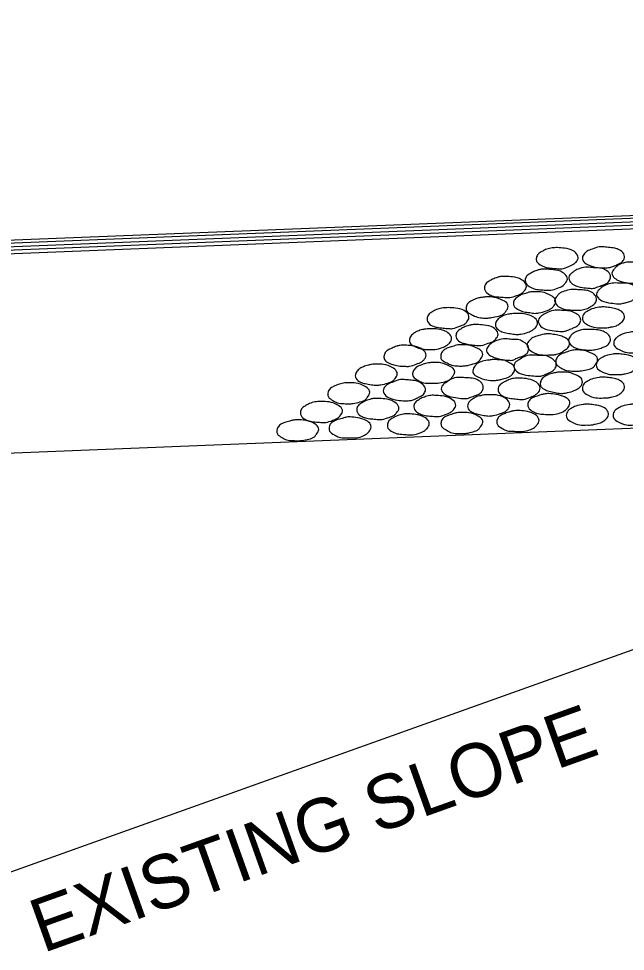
# Model space of a CAD drawing. Extents: x 3287 to 1767681, y -265 to 581440.
# Drawn here: x 3336.53 to 3350.12, y 48.55 to 69.44 of the extents above; entities that cross this region are included whole.
import ezdxf

# ---------------------------------------------------------------- set-up
doc = ezdxf.new("R2010")
doc.units = 0
doc.layers.add('R_Border PE', color=7, linetype='Continuous')

msp = doc.modelspace()

# ---------------------------------------------------------------- linework, layer by layer
at = {"layer": 'R_Border PE'}
for p, q in [((3332.136, 64.247), (3460.643, 69.373)), ((3332.286, 64.318), (3460.506, 69.441)), ((3331.799, 64.078), (3460.936, 69.227)), ((3331.966, 64.158), (3460.793, 69.3)), ((3331.631, 63.991), (3461.081, 69.155)), ((3321.917, 59.136), (3372.148, 61.138)), ((3361.044, 59.148), (3331.515, 48.595))]:
    msp.add_line(p, q, dxfattribs=at)
for points in [[(3348.599, 64.313), (3348.762, 64.298), (3348.958, 64.243), (3349.05, 64.146), (3349.066, 64.093), (3349.021, 63.989), (3348.973, 63.949), (3348.861, 63.891), (3348.699, 63.839), (3348.613, 63.839), (3348.487, 63.85), (3348.353, 63.868), (3348.245, 63.912), (3348.141, 63.994), (3348.128, 64.062), (3348.157, 64.148), (3348.233, 64.214), (3348.311, 64.255), (3348.421, 64.294), (3348.487, 64.306), (3348.599, 64.313)], [(3349.636, 63.857), (3349.469, 63.87), (3349.278, 63.934), (3349.172, 64.023), (3349.16, 64.086), (3349.21, 64.183), (3349.267, 64.232), (3349.382, 64.279), (3349.537, 64.331), (3349.615, 64.331), (3349.744, 64.318), (3349.885, 64.298), (3349.987, 64.261), (3350.087, 64.174), (3350.105, 64.114), (3350.076, 64.02), (3350, 63.962), (3349.924, 63.921), (3349.812, 63.878), (3349.744, 63.863), (3349.636, 63.857)], [(3350.299, 63.514), (3350.132, 63.528), (3349.935, 63.593), (3349.841, 63.677), (3349.823, 63.737), (3349.878, 63.836), (3349.93, 63.891), (3350.037, 63.954), (3350.199, 63.985), (3350.275, 63.985), (3350.399, 63.989), (3350.542, 63.967), (3350.653, 63.918), (3350.752, 63.831), (3350.768, 63.776), (3350.736, 63.672), (3350.661, 63.616), (3350.584, 63.583), (3350.474, 63.545), (3350.399, 63.522), (3350.299, 63.514)], [(3348.345, 63.829), (3348.51, 63.818), (3348.717, 63.758), (3348.811, 63.664), (3348.827, 63.608), (3348.77, 63.506), (3348.728, 63.462), (3348.607, 63.405), (3348.457, 63.358), (3348.368, 63.358), (3348.241, 63.365), (3348.104, 63.384), (3348, 63.426), (3347.895, 63.514), (3347.881, 63.577), (3347.911, 63.669), (3347.987, 63.727), (3348.063, 63.769), (3348.172, 63.811), (3348.241, 63.826), (3348.345, 63.829)], [(3349.325, 63.401), (3349.162, 63.42), (3348.968, 63.475), (3348.874, 63.567), (3348.856, 63.625), (3348.9, 63.724), (3348.961, 63.773), (3349.066, 63.831), (3349.23, 63.873), (3349.307, 63.873), (3349.437, 63.86), (3349.578, 63.85), (3349.684, 63.808), (3349.778, 63.718), (3349.794, 63.659), (3349.764, 63.566), (3349.694, 63.506), (3349.612, 63.472), (3349.502, 63.43), (3349.437, 63.405), (3349.325, 63.401)], [(3347.433, 63.664), (3347.598, 63.656), (3347.8, 63.593), (3347.894, 63.498), (3347.908, 63.443), (3347.86, 63.341), (3347.806, 63.292), (3347.69, 63.236), (3347.533, 63.195), (3347.452, 63.195), (3347.326, 63.205), (3347.185, 63.219), (3347.083, 63.258), (3346.981, 63.349), (3346.968, 63.41), (3346.999, 63.502), (3347.072, 63.562), (3347.148, 63.603), (3347.253, 63.646), (3347.326, 63.663), (3347.433, 63.664)], [(3349.969, 63.05), (3349.798, 63.071), (3349.597, 63.122), (3349.492, 63.216), (3349.477, 63.271), (3349.537, 63.37), (3349.589, 63.417), (3349.713, 63.486), (3349.866, 63.519), (3349.945, 63.519), (3350.071, 63.515), (3350.21, 63.502), (3350.317, 63.456), (3350.406, 63.363), (3350.422, 63.305), (3350.391, 63.216), (3350.32, 63.153), (3350.247, 63.114), (3350.142, 63.082), (3350.076, 63.064), (3349.969, 63.05)], [(3348.089, 63.318), (3348.258, 63.315), (3348.455, 63.239), (3348.546, 63.16), (3348.563, 63.095), (3348.51, 62.99), (3348.46, 62.946), (3348.351, 62.894), (3348.186, 62.849), (3348.107, 62.839), (3347.981, 62.855), (3347.847, 62.876), (3347.737, 62.92), (3347.632, 62.998), (3347.617, 63.064), (3347.648, 63.153), (3347.729, 63.218), (3347.801, 63.261), (3347.911, 63.295), (3347.981, 63.315), (3348.089, 63.318)], [(3349.018, 62.91), (3348.846, 62.92), (3348.647, 62.975), (3348.552, 63.075), (3348.536, 63.129), (3348.596, 63.226), (3348.638, 63.278), (3348.751, 63.333), (3348.906, 63.375), (3349, 63.375), (3349.123, 63.365), (3349.259, 63.355), (3349.364, 63.315), (3349.461, 63.221), (3349.477, 63.163), (3349.45, 63.071), (3349.377, 63.011), (3349.301, 62.964), (3349.183, 62.925), (3349.123, 62.914), (3349.018, 62.91)], [(3347.02, 63.21), (3347.185, 63.198), (3347.381, 63.129), (3347.486, 63.046), (3347.497, 62.993), (3347.445, 62.881), (3347.395, 62.825), (3347.28, 62.778), (3347.127, 62.744), (3347.041, 62.734), (3346.916, 62.737), (3346.771, 62.766), (3346.674, 62.813), (3346.57, 62.891), (3346.556, 62.952), (3346.583, 63.046), (3346.659, 63.111), (3346.734, 63.148), (3346.845, 63.185), (3346.915, 63.198), (3347.02, 63.21)], [(3346.151, 62.967), (3346.32, 62.956), (3346.512, 62.901), (3346.609, 62.805), (3346.62, 62.747), (3346.574, 62.647), (3346.525, 62.6), (3346.412, 62.551), (3346.252, 62.498), (3346.169, 62.498), (3346.045, 62.509), (3345.907, 62.527), (3345.799, 62.561), (3345.695, 62.655), (3345.682, 62.715), (3345.713, 62.808), (3345.787, 62.867), (3345.865, 62.914), (3345.977, 62.949), (3346.045, 62.961), (3346.151, 62.967)], [(3348.659, 62.435), (3348.486, 62.453), (3348.292, 62.506), (3348.19, 62.603), (3348.173, 62.66), (3348.227, 62.766), (3348.282, 62.808), (3348.393, 62.867), (3348.555, 62.91), (3348.634, 62.91), (3348.759, 62.901), (3348.897, 62.891), (3349.011, 62.838), (3349.105, 62.757), (3349.123, 62.69), (3349.089, 62.597), (3349.018, 62.54), (3348.937, 62.503), (3348.833, 62.462), (3348.759, 62.438), (3348.659, 62.435)], [(3349.629, 62.516), (3349.461, 62.519), (3349.278, 62.584), (3349.172, 62.674), (3349.16, 62.726), (3349.204, 62.838), (3349.267, 62.884), (3349.374, 62.938), (3349.537, 62.975), (3349.615, 62.983), (3349.743, 62.972), (3349.88, 62.951), (3349.987, 62.914), (3350.087, 62.828), (3350.105, 62.771), (3350.076, 62.677), (3350, 62.609), (3349.924, 62.563), (3349.809, 62.535), (3349.736, 62.519), (3349.629, 62.516)], [(3347.68, 62.838), (3347.852, 62.831), (3348.042, 62.771), (3348.141, 62.682), (3348.157, 62.624), (3348.109, 62.516), (3348.054, 62.472), (3347.947, 62.417), (3347.78, 62.375), (3347.699, 62.367), (3347.58, 62.381), (3347.444, 62.402), (3347.332, 62.44), (3347.227, 62.525), (3347.214, 62.584), (3347.242, 62.677), (3347.319, 62.744), (3347.392, 62.789), (3347.504, 62.818), (3347.583, 62.831), (3347.68, 62.838)], [(3345.757, 62.495), (3345.925, 62.488), (3346.121, 62.422), (3346.214, 62.334), (3346.231, 62.281), (3346.182, 62.171), (3346.129, 62.126), (3346.02, 62.071), (3345.859, 62.03), (3345.773, 62.026), (3345.651, 62.032), (3345.517, 62.053), (3345.406, 62.095), (3345.3, 62.174), (3345.286, 62.241), (3345.315, 62.328), (3345.397, 62.401), (3345.467, 62.44), (3345.58, 62.475), (3345.655, 62.488), (3345.757, 62.495)], [(3346.79, 62.588), (3346.962, 62.577), (3347.161, 62.522), (3347.256, 62.423), (3347.274, 62.368), (3347.221, 62.267), (3347.172, 62.22), (3347.054, 62.169), (3346.897, 62.119), (3346.818, 62.119), (3346.69, 62.131), (3346.551, 62.157), (3346.449, 62.184), (3346.342, 62.275), (3346.328, 62.338), (3346.358, 62.427), (3346.438, 62.488), (3346.512, 62.533), (3346.619, 62.567), (3346.69, 62.585), (3346.79, 62.588)], [(3349.317, 62.013), (3349.159, 62.029), (3348.964, 62.085), (3348.871, 62.173), (3348.853, 62.233), (3348.892, 62.328), (3348.952, 62.386), (3349.055, 62.443), (3349.223, 62.48), (3349.304, 62.48), (3349.435, 62.475), (3349.573, 62.459), (3349.678, 62.411), (3349.775, 62.323), (3349.791, 62.26), (3349.762, 62.171), (3349.691, 62.108), (3349.608, 62.072), (3349.495, 62.038), (3349.432, 62.024), (3349.317, 62.013)], [(3347.5, 61.791), (3347.337, 61.809), (3347.137, 61.87), (3347.028, 61.959), (3347.014, 62.022), (3347.067, 62.119), (3347.124, 62.169), (3347.238, 62.229), (3347.392, 62.267), (3347.479, 62.267), (3347.602, 62.255), (3347.746, 62.247), (3347.848, 62.194), (3347.944, 62.111), (3347.958, 62.045), (3347.928, 61.953), (3347.856, 61.898), (3347.784, 61.867), (3347.67, 61.825), (3347.606, 61.793), (3347.5, 61.791)], [(3348.4, 61.907), (3348.235, 61.911), (3348.034, 61.98), (3347.937, 62.072), (3347.921, 62.131), (3347.978, 62.234), (3348.029, 62.281), (3348.141, 62.328), (3348.304, 62.372), (3348.385, 62.381), (3348.51, 62.368), (3348.644, 62.344), (3348.751, 62.305), (3348.856, 62.226), (3348.874, 62.165), (3348.838, 62.069), (3348.759, 62.014), (3348.688, 61.959), (3348.583, 61.924), (3348.508, 61.911), (3348.4, 61.907)], [(3350.333, 61.959), (3350.165, 61.962), (3349.982, 62.027), (3349.875, 62.118), (3349.864, 62.17), (3349.908, 62.281), (3349.971, 62.328), (3350.077, 62.381), (3350.241, 62.419), (3350.319, 62.427), (3350.446, 62.415), (3350.584, 62.394), (3350.691, 62.357), (3350.791, 62.271), (3350.809, 62.215), (3350.78, 62.121), (3350.704, 62.053), (3350.627, 62.006), (3350.513, 61.979), (3350.44, 61.962), (3350.333, 61.959)], [(3345.179, 62.126), (3345.344, 62.114), (3345.548, 62.05), (3345.647, 61.956), (3345.661, 61.903), (3345.606, 61.794), (3345.561, 61.755), (3345.438, 61.704), (3345.284, 61.653), (3345.202, 61.653), (3345.074, 61.66), (3344.938, 61.684), (3344.833, 61.723), (3344.731, 61.804), (3344.716, 61.875), (3344.746, 61.962), (3344.822, 62.027), (3344.898, 62.063), (3345.004, 62.105), (3345.074, 62.123), (3345.179, 62.126)], [(3346.452, 62.137), (3346.617, 62.126), (3346.818, 62.053), (3346.915, 61.974), (3346.928, 61.919), (3346.873, 61.807), (3346.832, 61.759), (3346.711, 61.705), (3346.559, 61.668), (3346.468, 61.66), (3346.345, 61.663), (3346.201, 61.691), (3346.103, 61.742), (3345.999, 61.815), (3345.988, 61.885), (3346.017, 61.974), (3346.088, 62.038), (3346.168, 62.072), (3346.278, 62.108), (3346.342, 62.126), (3346.452, 62.137)], [(3348.11, 61.432), (3347.944, 61.45), (3347.745, 61.503), (3347.644, 61.6), (3347.627, 61.653), (3347.678, 61.759), (3347.742, 61.797), (3347.848, 61.867), (3348.012, 61.903), (3348.096, 61.903), (3348.217, 61.894), (3348.353, 61.888), (3348.463, 61.836), (3348.558, 61.754), (3348.575, 61.684), (3348.541, 61.594), (3348.465, 61.532), (3348.393, 61.5), (3348.285, 61.45), (3348.214, 61.433), (3348.11, 61.432)], [(3349.028, 62.021), (3349.188, 62.009), (3349.396, 61.932), (3349.489, 61.856), (3349.503, 61.794), (3349.45, 61.691), (3349.411, 61.636), (3349.291, 61.584), (3349.138, 61.552), (3349.044, 61.543), (3348.921, 61.547), (3348.777, 61.568), (3348.68, 61.621), (3348.579, 61.699), (3348.563, 61.763), (3348.599, 61.856), (3348.665, 61.919), (3348.743, 61.951), (3348.858, 61.99), (3348.918, 62.009), (3349.028, 62.021)], [(3349.94, 61.468), (3349.772, 61.472), (3349.589, 61.536), (3349.482, 61.627), (3349.471, 61.679), (3349.515, 61.79), (3349.578, 61.837), (3349.685, 61.89), (3349.848, 61.928), (3349.926, 61.936), (3350.054, 61.924), (3350.191, 61.903), (3350.298, 61.866), (3350.398, 61.78), (3350.416, 61.724), (3350.387, 61.63), (3350.311, 61.562), (3350.235, 61.515), (3350.12, 61.488), (3350.047, 61.472), (3349.94, 61.468)], [(3344.543, 61.702), (3344.708, 61.697), (3344.902, 61.628), (3345, 61.54), (3345.014, 61.485), (3344.967, 61.377), (3344.914, 61.328), (3344.805, 61.277), (3344.644, 61.238), (3344.556, 61.23), (3344.433, 61.239), (3344.297, 61.265), (3344.189, 61.298), (3344.09, 61.383), (3344.074, 61.443), (3344.105, 61.534), (3344.178, 61.605), (3344.254, 61.645), (3344.369, 61.678), (3344.437, 61.697), (3344.543, 61.702)], [(3345.82, 61.742), (3345.991, 61.731), (3346.187, 61.658), (3346.287, 61.577), (3346.303, 61.527), (3346.245, 61.416), (3346.2, 61.364), (3346.077, 61.307), (3345.925, 61.277), (3345.846, 61.273), (3345.719, 61.273), (3345.575, 61.293), (3345.472, 61.344), (3345.372, 61.422), (3345.357, 61.49), (3345.391, 61.577), (3345.461, 61.645), (3345.54, 61.678), (3345.648, 61.717), (3345.716, 61.731), (3345.82, 61.742)], [(3347.185, 61.335), (3347.017, 61.348), (3346.818, 61.416), (3346.716, 61.497), (3346.708, 61.552), (3346.753, 61.658), (3346.806, 61.713), (3346.92, 61.765), (3347.077, 61.794), (3347.161, 61.804), (3347.285, 61.797), (3347.429, 61.78), (3347.526, 61.734), (3347.628, 61.652), (3347.646, 61.59), (3347.614, 61.497), (3347.538, 61.429), (3347.467, 61.398), (3347.357, 61.364), (3347.29, 61.348), (3347.185, 61.335)], [(3348.688, 61.522), (3348.858, 61.516), (3349.041, 61.446), (3349.151, 61.364), (3349.16, 61.301), (3349.115, 61.196), (3349.052, 61.149), (3348.948, 61.099), (3348.782, 61.055), (3348.706, 61.045), (3348.583, 61.06), (3348.448, 61.086), (3348.332, 61.124), (3348.233, 61.204), (3348.217, 61.27), (3348.248, 61.357), (3348.321, 61.425), (3348.397, 61.467), (3348.51, 61.5), (3348.586, 61.516), (3348.688, 61.522)], [(3343.921, 61.281), (3344.087, 61.277), (3344.283, 61.207), (3344.382, 61.124), (3344.399, 61.073), (3344.344, 60.959), (3344.296, 60.904), (3344.178, 60.854), (3344.024, 60.819), (3343.943, 60.814), (3343.815, 60.817), (3343.67, 60.838), (3343.571, 60.888), (3343.472, 60.966), (3343.455, 61.029), (3343.487, 61.124), (3343.56, 61.189), (3343.637, 61.226), (3343.747, 61.262), (3343.812, 61.277), (3343.921, 61.281)], [(3345.184, 60.882), (3345.017, 60.893), (3344.818, 60.955), (3344.713, 61.048), (3344.699, 61.107), (3344.75, 61.21), (3344.807, 61.255), (3344.928, 61.304), (3345.089, 61.356), (3345.168, 61.356), (3345.294, 61.344), (3345.431, 61.328), (3345.533, 61.285), (3345.626, 61.2), (3345.645, 61.136), (3345.613, 61.042), (3345.545, 60.985), (3345.475, 60.95), (3345.367, 60.9), (3345.287, 60.885), (3345.184, 60.882)], [(3346.483, 60.93), (3346.316, 60.951), (3346.121, 61.003), (3346.015, 61.097), (3345.998, 61.15), (3346.053, 61.255), (3346.108, 61.294), (3346.223, 61.365), (3346.379, 61.404), (3346.465, 61.404), (3346.586, 61.393), (3346.729, 61.383), (3346.837, 61.335), (3346.925, 61.247), (3346.941, 61.183), (3346.912, 61.094), (3346.842, 61.029), (3346.768, 60.998), (3346.654, 60.959), (3346.591, 60.935), (3346.483, 60.93)], [(3347.737, 61.387), (3347.898, 61.377), (3348.104, 61.314), (3348.199, 61.222), (3348.214, 61.16), (3348.164, 61.06), (3348.11, 61.016), (3347.997, 60.963), (3347.84, 60.913), (3347.754, 60.913), (3347.627, 60.925), (3347.491, 60.948), (3347.384, 60.982), (3347.289, 61.069), (3347.271, 61.134), (3347.302, 61.226), (3347.373, 61.281), (3347.452, 61.322), (3347.562, 61.369), (3347.627, 61.383), (3347.737, 61.387)], [(3349.629, 60.945), (3349.461, 60.948), (3349.278, 61.013), (3349.172, 61.103), (3349.16, 61.155), (3349.204, 61.267), (3349.267, 61.313), (3349.374, 61.367), (3349.537, 61.404), (3349.615, 61.412), (3349.743, 61.401), (3349.88, 61.38), (3349.987, 61.343), (3350.087, 61.257), (3350.105, 61.2), (3350.076, 61.106), (3350, 61.038), (3349.924, 60.992), (3349.809, 60.964), (3349.736, 60.948), (3349.629, 60.945)], [(3347.062, 61.016), (3347.227, 61.011), (3347.423, 60.945), (3347.517, 60.856), (3347.533, 60.799), (3347.488, 60.689), (3347.436, 60.644), (3347.326, 60.594), (3347.161, 60.55), (3347.077, 60.54), (3346.955, 60.553), (3346.821, 60.578), (3346.711, 60.618), (3346.606, 60.699), (3346.591, 60.764), (3346.62, 60.851), (3346.701, 60.919), (3346.771, 60.963), (3346.883, 60.995), (3346.959, 61.011), (3347.062, 61.016)], [(3348.41, 61.042), (3348.578, 61.024), (3348.762, 60.966), (3348.871, 60.88), (3348.88, 60.822), (3348.835, 60.722), (3348.774, 60.667), (3348.665, 60.61), (3348.508, 60.574), (3348.424, 60.574), (3348.3, 60.578), (3348.164, 60.594), (3348.054, 60.641), (3347.952, 60.73), (3347.936, 60.793), (3347.966, 60.882), (3348.039, 60.948), (3348.117, 60.977), (3348.23, 61.013), (3348.304, 61.032), (3348.41, 61.042)], [(3343.312, 60.867), (3343.485, 60.854), (3343.67, 60.793), (3343.773, 60.702), (3343.786, 60.641), (3343.731, 60.54), (3343.683, 60.497), (3343.571, 60.443), (3343.411, 60.395), (3343.333, 60.395), (3343.204, 60.405), (3343.068, 60.421), (3342.96, 60.463), (3342.858, 60.55), (3342.845, 60.617), (3342.872, 60.704), (3342.948, 60.764), (3343.024, 60.807), (3343.138, 60.848), (3343.204, 60.861), (3343.312, 60.867)], [(3344.571, 60.932), (3344.736, 60.922), (3344.938, 60.861), (3345.035, 60.767), (3345.051, 60.709), (3344.996, 60.61), (3344.949, 60.561), (3344.833, 60.51), (3344.674, 60.463), (3344.594, 60.463), (3344.466, 60.473), (3344.33, 60.492), (3344.225, 60.529), (3344.12, 60.617), (3344.108, 60.68), (3344.137, 60.77), (3344.215, 60.83), (3344.288, 60.874), (3344.399, 60.913), (3344.466, 60.93), (3344.571, 60.932)], [(3345.852, 61.003), (3346.02, 60.99), (3346.208, 60.93), (3346.313, 60.835), (3346.323, 60.775), (3346.271, 60.678), (3346.223, 60.633), (3346.111, 60.579), (3345.951, 60.529), (3345.87, 60.529), (3345.74, 60.54), (3345.606, 60.555), (3345.499, 60.599), (3345.401, 60.684), (3345.385, 60.749), (3345.414, 60.838), (3345.486, 60.898), (3345.566, 60.945), (3345.677, 60.982), (3345.74, 60.998), (3345.852, 61.003)], [(3349.269, 60.339), (3349.101, 60.342), (3348.918, 60.407), (3348.812, 60.498), (3348.8, 60.549), (3348.844, 60.661), (3348.907, 60.708), (3349.014, 60.761), (3349.177, 60.798), (3349.255, 60.807), (3349.383, 60.795), (3349.52, 60.774), (3349.627, 60.737), (3349.727, 60.651), (3349.745, 60.595), (3349.716, 60.501), (3349.64, 60.433), (3349.564, 60.386), (3349.449, 60.358), (3349.376, 60.342), (3349.269, 60.339)], [(3350.317, 60.339), (3350.148, 60.342), (3349.966, 60.407), (3349.859, 60.498), (3349.848, 60.549), (3349.891, 60.661), (3349.954, 60.708), (3350.061, 60.761), (3350.224, 60.798), (3350.302, 60.807), (3350.43, 60.795), (3350.567, 60.774), (3350.674, 60.737), (3350.775, 60.651), (3350.792, 60.595), (3350.763, 60.501), (3350.687, 60.433), (3350.611, 60.386), (3350.496, 60.358), (3350.423, 60.342), (3350.317, 60.339)], [(3346.457, 60.621), (3346.62, 60.613), (3346.824, 60.54), (3346.918, 60.461), (3346.933, 60.405), (3346.876, 60.295), (3346.837, 60.243), (3346.714, 60.189), (3346.564, 60.152), (3346.473, 60.147), (3346.35, 60.149), (3346.206, 60.173), (3346.108, 60.227), (3346.006, 60.304), (3345.993, 60.369), (3346.02, 60.461), (3346.095, 60.526), (3346.172, 60.558), (3346.284, 60.595), (3346.349, 60.613), (3346.457, 60.621)], [(3347.724, 60.663), (3347.884, 60.647), (3348.075, 60.587), (3348.173, 60.5), (3348.19, 60.443), (3348.143, 60.34), (3348.089, 60.286), (3347.979, 60.23), (3347.818, 60.194), (3347.737, 60.194), (3347.609, 60.198), (3347.473, 60.21), (3347.363, 60.262), (3347.259, 60.346), (3347.245, 60.413), (3347.277, 60.505), (3347.352, 60.565), (3347.429, 60.599), (3347.538, 60.633), (3347.614, 60.655), (3347.724, 60.663)], [(3342.777, 60.456), (3342.947, 60.443), (3343.147, 60.377), (3343.241, 60.293), (3343.256, 60.241), (3343.204, 60.13), (3343.159, 60.076), (3343.036, 60.021), (3342.884, 59.992), (3342.803, 59.986), (3342.68, 59.989), (3342.536, 60.005), (3342.431, 60.06), (3342.329, 60.138), (3342.314, 60.201), (3342.343, 60.293), (3342.418, 60.361), (3342.492, 60.395), (3342.605, 60.427), (3342.677, 60.443), (3342.777, 60.456)], [(3343.958, 60.519), (3344.123, 60.502), (3344.317, 60.44), (3344.414, 60.353), (3344.428, 60.298), (3344.385, 60.194), (3344.331, 60.144), (3344.221, 60.083), (3344.058, 60.049), (3343.974, 60.049), (3343.849, 60.052), (3343.713, 60.066), (3343.605, 60.12), (3343.498, 60.201), (3343.487, 60.267), (3343.513, 60.359), (3343.594, 60.419), (3343.663, 60.453), (3343.783, 60.485), (3343.854, 60.51), (3343.958, 60.519)], [(3345.262, 60.587), (3345.428, 60.574), (3345.616, 60.515), (3345.719, 60.421), (3345.732, 60.363), (3345.682, 60.262), (3345.632, 60.217), (3345.524, 60.162), (3345.364, 60.117), (3345.276, 60.117), (3345.15, 60.128), (3345.014, 60.144), (3344.907, 60.183), (3344.805, 60.27), (3344.794, 60.332), (3344.818, 60.424), (3344.894, 60.482), (3344.972, 60.526), (3345.087, 60.568), (3345.15, 60.583), (3345.262, 60.587)]]:
    msp.add_spline(points, degree=3, dxfattribs=at)

# ---------------------------------------------------------------- texts
msp.add_text('EXISTING SLOPE', height=1.2, rotation=19.6609, dxfattribs=at).set_placement((3337.073, 48.504))

doc.saveas('drawing.dxf')
